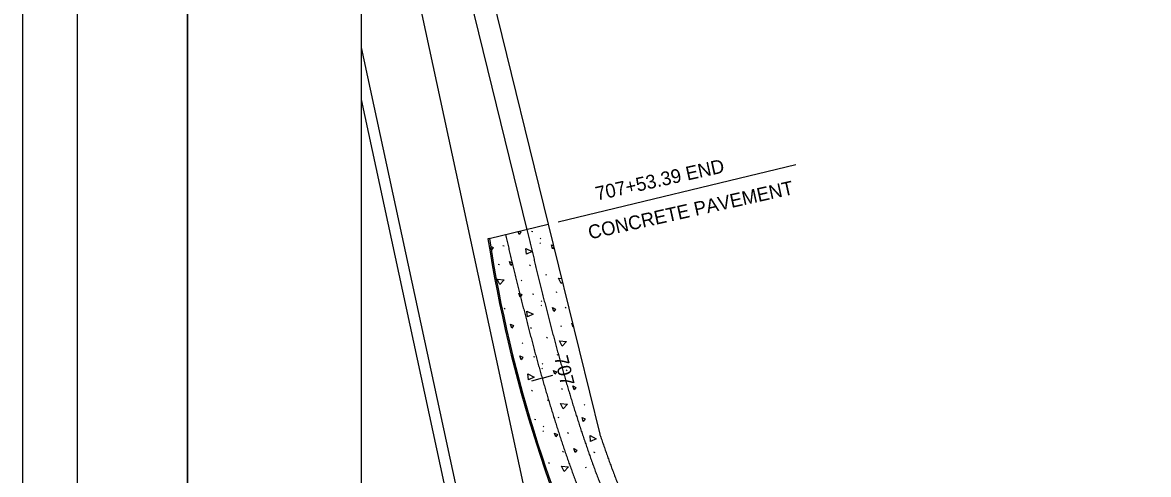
# Model space of a CAD drawing. Extents: x 0 to 1360, y 0 to 880.
# Drawn here: x 0 to 409.3, y 310.5 to 474.6 of the extents above; entities that cross this region are included whole.
import ezdxf

# ---------------------------------------------------------------- set-up
doc = ezdxf.new("R2010")
doc.units = 0
for name, color, linetype in [('Default', 7, 'Continuous'), ('PV_X_Curb', 7, 'Continuous'), ('PV_X_Shoulder', 7, 'Continuous'), ('RD_X_Concrete_Pad', 7, 'Continuous'), ('SH_Border', 7, 'Continuous'), ('SH_Cut_Line', 7, 'Continuous'), ('SH_Text', 7, 'Continuous')]:
    doc.layers.add(name, color=color, linetype=linetype)

msp = doc.modelspace()

# ---------------------------------------------------------------- linework, layer by layer
at = {"layer": 'Default'}
for p, q in [((123.28, 644.12), (183.33, 399.37)), ((243.77, 21.21), (123.28, 579.31)), ((219.22, 21.21), (123.28, 465.59)), ((215.13, 21.21), (123.28, 446.64)), ((194.74, 402.26), (281.05, 423.14)), ((185.06, 398.88), (185.46, 398.71)), ((169.69, 396.2), (169.2, 396.12)), ((174.66, 393.66), (175.06, 393.49)), ((188.32, 394.64), (188.05, 394.45)), ((188.39, 396.31), (188.13, 396.13)), ((172.95, 386.88), (173.35, 386.71)), ((184.24, 386.62), (184.64, 386.45)), ((181.48, 381.02), (181.22, 380.84)), ((190.11, 383.12), (190.51, 382.95)), ((194.25, 376.67), (193.85, 376.62)), ((185.43, 376.11), (185.83, 375.94)), ((188.76, 373.55), (188.5, 373.37)), ((175.03, 370.89), (175.44, 370.72)), ((188.69, 371.87), (188.42, 371.69)), ((197.27, 371.25), (197.67, 371.08)), ((195.56, 364.48), (195.96, 364.31)), ((184.61, 363.85), (185.01, 363.68)), ((190.48, 360.35), (190.88, 360.18)), ((181.86, 358.26), (181.59, 358.08)), ((185.8, 353.35), (186.2, 353.18)), ((194.62, 353.9), (194.22, 353.85)), ((189.06, 349.1), (188.79, 348.92)), ((189.13, 350.78), (188.87, 350.6)), ((197.64, 348.49), (198.04, 348.32)), ((188.9, 345.43), (185.05, 344.33)), ((188.9, 345.43), (192.75, 346.52)), ((184.98, 341.09), (185.38, 340.92)), ((195.93, 341.71), (196.33, 341.54)), ((190.85, 337.59), (191.25, 337.42)), ((204.46, 335.86), (204.2, 335.67)), ((186.17, 330.58), (186.57, 330.41)), ((189.5, 328.02), (189.24, 327.84)), ((194.99, 331.14), (194.59, 331.09)), ((208.41, 330.95), (208.41, 330.94)), ((189.43, 326.34), (189.17, 326.16)), ((198.01, 325.72), (198.42, 325.55)), ((196.3, 318.95), (196.7, 318.77)), ((207.59, 318.69), (207.99, 318.51)), ((191.22, 314.82), (191.62, 314.65)), ((204.84, 313.09), (204.57, 312.91))]:
    msp.add_line(p, q, dxfattribs=at)
for points in [[(180.62, 398.84), (181.15, 398.6), (180.5, 397.7), (180.16, 398.73)], [(170.13, 393.43), (171.12, 392.98), (170.47, 392.08), (170.23, 392.79)], [(192.24, 393.86), (193.02, 393.5)], [(193.13, 393.03), (192.71, 392.44), (192.24, 393.86)], [(182.94, 392.59), (185.22, 391.43), (183.15, 390.47), (182.94, 392.55)], [(177.04, 387.83), (178.16, 387.31), (177.51, 386.41), (177.04, 387.83)], [(172.58, 381.47), (175.12, 381.16), (173.51, 379.54), (172.6, 381.43)], [(194.82, 381.83), (195.92, 381.7)], [(196.24, 380.4), (195.75, 379.91), (194.83, 381.79)], [(180.41, 376.34), (181.52, 375.83), (180.87, 374.93), (180.41, 376.34)], [(183.31, 369.83), (185.59, 368.67), (183.52, 367.7), (183.31, 369.78)], [(192.61, 371.09), (193.73, 370.57), (193.08, 369.68), (192.61, 371.09)], [(177.42, 365.06), (178.53, 364.55), (177.88, 363.65), (177.42, 365.06)], [(199.65, 365.42), (199.96, 365.28)], [(200.23, 364.17), (200.12, 364.01), (199.65, 365.42)], [(195.19, 359.07), (197.73, 358.76), (196.12, 357.14), (195.21, 359.03)], [(180.78, 353.58), (181.9, 353.06), (181.24, 352.16), (180.78, 353.58)], [(192.98, 348.32), (194.1, 347.81), (193.45, 346.91), (192.98, 348.32)], [(183.68, 347.06), (185.96, 345.9), (183.89, 344.93), (183.68, 347.02)], [(200.02, 342.66), (201.14, 342.14), (200.49, 341.24), (200.02, 342.66)], [(195.56, 336.3), (198.1, 335.99), (196.49, 334.38), (195.58, 336.26)], [(203.39, 331.17), (204.5, 330.66), (203.85, 329.76), (203.39, 331.17)], [(193.35, 325.56), (194.47, 325.04), (193.82, 324.14), (193.35, 325.56)], [(206.29, 324.66), (208.57, 323.5), (206.5, 322.53), (206.29, 324.61)], [(200.4, 319.89), (201.51, 319.38), (200.86, 318.48), (200.4, 319.89)], [(195.93, 313.54), (198.47, 313.23), (196.86, 311.61), (195.95, 313.5)]]:
    msp.add_lwpolyline(points, dxfattribs=at)
for radius in [486.96, 486.46]:
    msp.add_arc((650.45, 470.48), radius, 188.7836, 206.7998, dxfattribs=at)
for points in [[(175.53, 397.61), (176, 395.64), (176.48, 393.67), (176.96, 391.7), (177.43, 389.73), (177.91, 387.76), (178.39, 385.79), (178.88, 383.82), (179.36, 381.85), (179.84, 379.89), (180.33, 377.92), (180.82, 375.95), (181.31, 373.99), (181.8, 372.02), (182.3, 370.05), (182.8, 368.09), (183.31, 366.13), (183.81, 364.16), (184.32, 362.2), (184.84, 360.24), (185.36, 358.28), (185.88, 356.32), (186.41, 354.37), (186.95, 352.41), (187.48, 350.46), (188.03, 348.51), (188.58, 346.55), (189.13, 344.6), (189.7, 342.66), (190.26, 340.71), (190.84, 338.77), (191.42, 336.83), (192.01, 334.89), (192.6, 332.95), (193.2, 331.01), (193.81, 329.08), (194.43, 327.15), (195.06, 325.22), (195.69, 323.3), (196.33, 321.37), (196.98, 319.45), (197.64, 317.54), (198.31, 315.62), (198.99, 313.71), (199.68, 311.81), (200.38, 309.9), (201.08, 308), (201.8, 306.11), (202.53, 304.21), (203.26, 302.33), (204.01, 300.44), (204.77, 298.56), (205.54, 296.69), (206.32, 294.82), (207.11, 292.95), (207.92, 291.09), (208.73, 289.23), (209.56, 287.38), (210.4, 285.54), (211.25, 283.7), (212.11, 281.87), (212.99, 280.04), (213.88, 278.22), (214.78, 276.4), (215.7, 274.59), (216.63, 272.79), (217.57, 271), (218.53, 269.21), (219.5, 267.43), (220.48, 265.66), (221.48, 263.89), (222.49, 262.14), (223.51, 260.39), (224.55, 258.65), (225.61, 256.92)], [(183.3, 399.49), (183.78, 397.52), (184.25, 395.55), (184.73, 393.59), (185.21, 391.62), (185.69, 389.65), (186.17, 387.69), (186.65, 385.73), (187.13, 383.76), (187.61, 381.8), (188.09, 379.84), (188.58, 377.89), (189.07, 375.93), (189.56, 373.98), (190.06, 372.02), (190.55, 370.07), (191.05, 368.12), (191.56, 366.17), (192.06, 364.23), (192.57, 362.28), (193.09, 360.34), (193.61, 358.4), (194.13, 356.46), (194.66, 354.53), (195.19, 352.59), (195.73, 350.66), (196.28, 348.74), (196.82, 346.81), (197.38, 344.89), (197.94, 342.97), (198.51, 341.05), (199.08, 339.13), (199.66, 337.22), (200.24, 335.31), (200.84, 333.4), (201.44, 331.5), (202.05, 329.6), (202.66, 327.71), (203.28, 325.81), (203.92, 323.92), (204.56, 322.04), (205.2, 320.16), (205.86, 318.28), (206.52, 316.41), (207.2, 314.54), (207.88, 312.67), (208.57, 310.81), (209.27, 308.95), (209.99, 307.1), (210.71, 305.26), (211.44, 303.42), (212.18, 301.58), (212.93, 299.75), (213.69, 297.92), (214.47, 296.1), (215.25, 294.29), (216.05, 292.48), (216.85, 290.67), (217.67, 288.88), (218.5, 287.09), (219.34, 285.3), (220.19, 283.52), (221.06, 281.75), (221.93, 279.99), (222.82, 278.23), (223.73, 276.48), (224.64, 274.74), (225.57, 273.01), (226.51, 271.28), (227.46, 269.57), (228.43, 267.86), (229.41, 266.16), (230.4, 264.46), (231.4, 262.78), (232.44, 261.08)]]:
    msp.add_spline(points, degree=3, dxfattribs=at)
at = {"layer": 'PV_X_Curb'}
msp.add_arc((650.45, 470.48), 486.46, 188.7836, 206.7998, dxfattribs=at)
at = {"layer": 'PV_X_Shoulder'}
msp.add_line((130.56, 647.99), (191.08, 401.37), dxfattribs=at)
at = {"layer": 'RD_X_Concrete_Pad'}
for p, q in [((169.69, 396.2), (191.08, 401.37)), ((191.08, 401.37), (209.84, 325.12))]:
    msp.add_line(p, q, dxfattribs=at)
msp.add_spline([(209.84, 325.12), (209.91, 324.93), (210.54, 323.07), (211.18, 321.21), (211.83, 319.36), (212.48, 317.52), (213.14, 315.67), (213.82, 313.84), (214.5, 312.01), (215.19, 310.18), (215.89, 308.36), (216.6, 306.54), (217.32, 304.73), (218.04, 302.93), (218.78, 301.13), (219.53, 299.34), (220.29, 297.55), (221.06, 295.77), (221.84, 294), (222.63, 292.23), (223.43, 290.47), (224.24, 288.71), (225.07, 286.97), (225.9, 285.23), (226.75, 283.49), (227.6, 281.77), (228.47, 280.05), (229.36, 278.34), (230.25, 276.64), (231.15, 274.95), (232.07, 273.26), (233, 271.59), (233.94, 269.92), (234.9, 268.26), (235.87, 266.61), (236.85, 264.97), (237.87, 263.29)], degree=3, dxfattribs=at)
at = {"layer": 'SH_Border'}
for points in [[(20, 860), (60, 860), (60, 20), (20, 20)], [(60, 860), (1340, 860), (1340, 20), (60, 20)]]:
    msp.add_lwpolyline(points, close=True, dxfattribs=at)
at = {"layer": 'SH_Cut_Line'}
msp.add_lwpolyline([(0, 0), (1360, 0), (1360, 880), (0, 880)], close=True, dxfattribs=at)
at = {"layer": 'SH_Text'}
msp.add_line((123.28, 55.38), (123.28, 703.37), dxfattribs=at)

# ---------------------------------------------------------------- texts
at = {"layer": 'Default'}
for s, rotation, p in [('707+53.39 END', 12.5122, (208.85, 409.95)), ('CONCRETE PAVEMENT', 12.5122, (206.23, 395.86)), ('707', 283.9142, (193.22, 353.06))]:
    msp.add_text(s, height=5, rotation=rotation, dxfattribs=at).set_placement(p)

doc.saveas('drawing.dxf')
